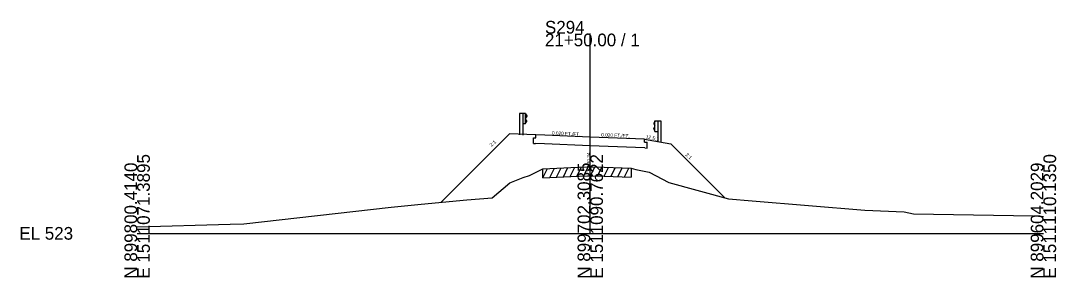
# Model space of a CAD drawing. Extents: x 974 to 2203, y -10 to 19041.
# Drawn here: x 1974.3 to 2202.8, y 2990.3 to 3046.9 of the extents above; entities that cross this region are included whole.
import ezdxf

# ---------------------------------------------------------------- set-up
doc = ezdxf.new("R2010")
doc.units = 0
for name, color, linetype in [('RD_GPK_XS_Cell', 7, 'Continuous'), ('RD_XS_Base', 7, 'Continuous'), ('RD_XS_EarthShd', 7, 'Continuous'), ('RD_XS_ExGround', 7, 'Continuous'), ('RD_XS_ExPaveRet', 7, 'Continuous'), ('RD_XS_GR', 7, 'Continuous'), ('RD_XS_Pave', 7, 'Continuous'), ('RD_XS_TX_Elev_EX', 7, 'Continuous'), ('RD_XS_TX_Slope', 7, 'Continuous')]:
    doc.layers.add(name, color=color, linetype=linetype)

msp = doc.modelspace()

# ---------------------------------------------------------------- linework, layer by layer
at = {"layer": 'RD_GPK_XS_Cell'}
for p, q in [((2100, 3000), (2100, 3044.06)), ((2000, 3000), (2100, 3000)), ((2100, 3000), (2200, 3000))]:
    msp.add_line(p, q, dxfattribs=at)
at = {"layer": 'RD_XS_Base'}
for p, q in [((2088, 3021.06), (2088, 3021.7)), ((2087.5, 3019.81), (2087.5, 3021.08)), ((2087.5, 3021.08), (2088, 3021.06)), ((2087.5, 3019.81), (2087.89, 3019.8)), ((2089.89, 3019.72), (2087.89, 3019.8)), ((2099.95, 3019.32), (2089.89, 3019.72)), ((2110, 3018.91), (2099.98, 3019.31)), ((2112, 3020.1), (2112, 3020.74)), ((2112, 3020.1), (2112.52, 3020.08)), ((2112.52, 3018.81), (2112.52, 3020.08)), ((2112.02, 3018.83), (2110, 3018.91)), ((2112.02, 3018.83), (2112.52, 3018.81))]:
    msp.add_line(p, q, dxfattribs=at)
at = {"layer": 'RD_XS_EarthShd'}
for p, q in [((2067.12, 3006.85), (2082.2, 3021.93)), ((2086, 3021.78), (2082.2, 3021.93)), ((2088, 3021.7), (2086, 3021.78)), ((2112, 3020.74), (2114, 3020.41)), ((2114, 3020.41), (2117.75, 3019.78)), ((2129.72, 3007.81), (2117.75, 3019.78))]:
    msp.add_line(p, q, dxfattribs=at)
at = {"layer": 'RD_XS_ExGround'}
msp.add_lwpolyline([(2000, 3001.46), (2020.51, 3002), (2023.51, 3002.12), (2056.07, 3005.74), (2062.68, 3006.43), (2072.79, 3007.39), (2078.38, 3007.85), (2082.24, 3011.15), (2085.19, 3012.35), (2086.61, 3012.75), (2089.56, 3014.24), (2095.71, 3014.53), (2099.4, 3014.69), (2100, 3014.67), (2103.08, 3014.6), (2109, 3014.37), (2110.04, 3014.08), (2113.02, 3013.51), (2117.37, 3011.19), (2130.52, 3007.59), (2135.75, 3007.17), (2160.6, 3005.11), (2169.24, 3004.74), (2171.35, 3004.33), (2197.81, 3003.84), (2200, 3003.73)], dxfattribs=at)
at = {"layer": 'RD_XS_ExPaveRet'}
for p, q in [((2091.06, 3012.31), (2092.08, 3014.36)), ((2092.56, 3012.38), (2093.58, 3014.43)), ((2094.06, 3012.45), (2095.08, 3014.5)), ((2095.56, 3012.52), (2096.58, 3014.57)), ((2097.06, 3012.59), (2098.08, 3014.63)), ((2098.56, 3012.65), (2099.57, 3014.68)), ((2100.06, 3012.67), (2101.04, 3014.65)), ((2101.56, 3012.64), (2102.54, 3014.61)), ((2103.06, 3012.6), (2104.04, 3014.56)), ((2104.56, 3012.54), (2105.54, 3014.51)), ((2106.06, 3012.49), (2107.04, 3014.45)), ((2107.56, 3012.43), (2108.54, 3014.39)), ((2109, 3014.37), (2109, 3012.37)), ((2089.56, 3012.24), (2090.58, 3014.29)), ((2089.56, 3012.24), (2089.56, 3014.24)), ((2089.56, 3012.24), (2095.71, 3012.53)), ((2095.71, 3012.53), (2099.4, 3012.69)), ((2099.4, 3012.69), (2100, 3012.67)), ((2100, 3012.67), (2103.08, 3012.6)), ((2103.08, 3012.6), (2109, 3012.37))]:
    msp.add_line(p, q, dxfattribs=at)
at = {"layer": 'RD_XS_GR'}
for p, q in [((2084.41, 3026.47), (2084.41, 3021.71)), ((2085.08, 3026.47), (2084.41, 3026.47)), ((2085.08, 3026.47), (2085.08, 3021.68)), ((2085.74, 3026.47), (2085.08, 3026.47)), ((2085.74, 3024.14), (2085.74, 3026.47)), ((2085.74, 3026.33), (2086.01, 3025.93)), ((2086.01, 3025.83), (2085.74, 3025.43)), ((2086.01, 3025.93), (2086.01, 3025.83)), ((2085.74, 3024.14), (2085.08, 3024.14)), ((2086.01, 3024.79), (2085.74, 3025.19)), ((2085.74, 3024.29), (2086.01, 3024.69)), ((2086.01, 3024.69), (2086.01, 3024.79)), ((2114.27, 3024.68), (2114, 3024.28)), ((2114, 3024.28), (2114, 3024.18)), ((2114, 3024.18), (2114.27, 3023.78)), ((2114, 3023.14), (2114.27, 3023.54)), ((2114.27, 3024.83), (2114.94, 3024.83)), ((2114.27, 3022.49), (2114.27, 3024.83)), ((2114.94, 3024.83), (2114.94, 3020.17)), ((2114.94, 3024.83), (2115.6, 3024.83)), ((2115.6, 3024.83), (2115.6, 3020.06)), ((2114, 3023.04), (2114, 3023.14)), ((2114.27, 3022.64), (2114, 3023.04)), ((2114.27, 3022.49), (2114.94, 3022.49))]:
    msp.add_line(p, q, dxfattribs=at)
at = {"layer": 'RD_XS_Pave'}
for p, q in [((2090, 3021.62), (2088, 3021.7)), ((2100, 3021.22), (2090, 3021.62)), ((2110, 3020.82), (2100, 3021.22)), ((2112, 3020.74), (2110, 3020.82))]:
    msp.add_line(p, q, dxfattribs=at)

# ---------------------------------------------------------------- texts
at = {"layer": 'RD_GPK_XS_Cell'}
for s, p in [('S294', (2090, 3044.06)), ('21+50.00 / 1', (2090, 3041.26)), ('EL 523', (1974, 2998.6))]:
    msp.add_text(s, height=2.8, dxfattribs=at).set_placement(p)
for s, p in [('E 1511071.3895', (2002.8, 2990)), ('E 1511090.7622', (2102.8, 2990)), ('E 1511110.1350', (2202.8, 2990)), ('N 899800.4140', (2000, 2990)), ('N 899702.3085', (2100, 2990)), ('N 899604.2029', (2200, 2990))]:
    msp.add_text(s, height=2.8, rotation=90, dxfattribs=at).set_placement(p)
at = {"layer": 'RD_XS_TX_Elev_EX'}
msp.add_text('530.34', height=0.75, rotation=90, dxfattribs=at).set_placement((2100, 3014.67))
at = {"layer": 'RD_XS_TX_Slope'}
for s, height, rotation, p in [('0.020 FT./FT.', 0.7518, 357.7673, (2091.53, 3021.75)), ('0.020 FT./FT.', 0.7518, 357.604, (2102.4, 3021.38)), ('12.5:1', 0.778, 347.2489, (2112.17, 3020.99)), ('2:1', 0.778, 40.6589, (2078.18, 3019.08)), ('2:1', 0.778, 319.3411, (2120.92, 3017.24))]:
    msp.add_text(s, height=height, rotation=rotation, dxfattribs=at).set_placement(p)

doc.saveas('drawing.dxf')
